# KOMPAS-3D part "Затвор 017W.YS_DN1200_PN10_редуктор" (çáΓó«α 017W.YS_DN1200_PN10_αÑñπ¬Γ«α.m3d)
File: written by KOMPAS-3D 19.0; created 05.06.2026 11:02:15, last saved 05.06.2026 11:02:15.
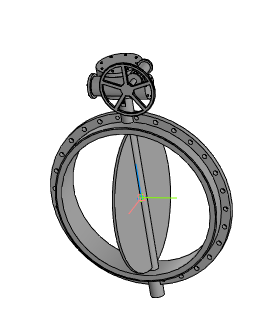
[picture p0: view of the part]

Document properties: Автор: Энергия; Полное имя файла: ..\..\..\3d для проектировщиков\x.x Тип 017W.Y(S) Затвор дисковый поворотный межфланцевый\Затвор 017W.Y(S)_DN50-DN1200_редуктор\Затвор 017W.YS_DN1200_PN10_редуктор.a3d

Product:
- Part/product: Затвор 017W.YS_DN1200_PN10_редуктор
    Масса: 1026.09

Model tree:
1. Операция без истории:1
